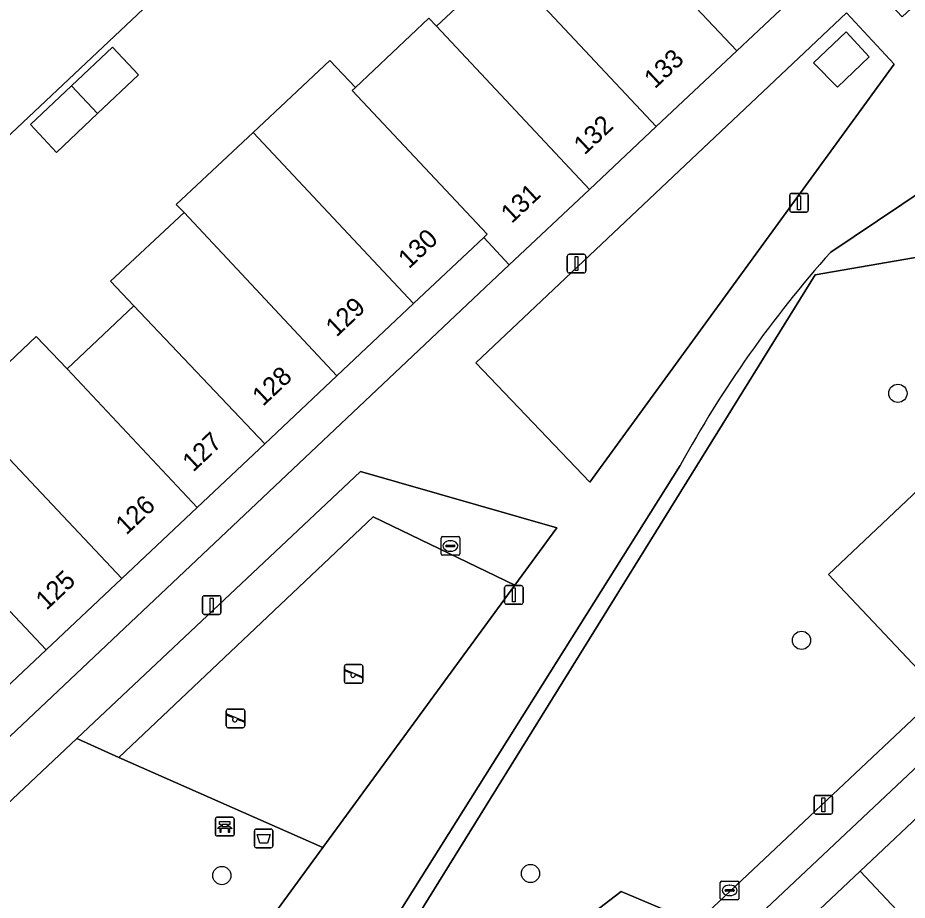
# Model space of a CAD drawing. Extents: x 162542 to 163147, y 380779 to 381521.
# Drawn here: x 162864.72 to 162912.36, y 381319.49 to 381366.74 of the extents above; entities that cross this region are included whole.
import ezdxf

# ---------------------------------------------------------------- set-up
doc = ezdxf.new("R2010")
doc.units = 0
for name, color, linetype in [('IMGEO_Afvalbak', 7, 'Continuous'), ('IMGEO_Bank', 7, 'Continuous'), ('IMGEO_Boom', 7, 'Continuous'), ('IMGEO_Erf', 7, 'Continuous'), ('IMGEO_Groenvoorziening', 7, 'Continuous'), ('IMGEO_Lage_trafo', 7, 'Continuous'), ('IMGEO_Lichtmast', 7, 'Continuous'), ('IMGEO_Muur', 7, 'Continuous'), ('IMGEO_Pand', 7, 'Continuous'), ('IMGEO_Pand_nummerreeks', 7, 'Continuous'), ('IMGEO_Rijbaan_lokaal_open', 7, 'Continuous'), ('IMGEO_Rioolput', 7, 'Continuous'), ('IMGEO_Speelvoorziening', 7, 'Continuous'), ('IMGEO_Terreindeel_halfverhard', 7, 'Continuous'), ('IMGEO_Terreindeel_zand', 7, 'Continuous'), ('IMGEO_Voetpad_open', 7, 'Continuous')]:
    doc.layers.add(name, color=color, linetype=linetype)

msp = doc.modelspace()

# ---------------------------------------------------------------- linework, layer by layer
at = {"layer": 'IMGEO_Afvalbak'}
for p, q in [((162877.394, 381322.396), (162877.394, 381323.196)), ((162877.394, 381323.196), (162877.394, 381322.396)), ((162877.494, 381323.296), (162878.284, 381323.296)), ((162878.284, 381323.296), (162877.494, 381323.296)), ((162878.384, 381323.196), (162878.384, 381322.396)), ((162878.384, 381322.396), (162878.384, 381323.196)), ((162878.284, 381322.296), (162877.494, 381322.296)), ((162877.494, 381322.296), (162878.284, 381322.296))]:
    msp.add_line(p, q, dxfattribs=at)
msp.add_lwpolyline([(162877.537, 381323.01), (162878.241, 381323.01), (162878.092, 381322.54), (162877.686, 381322.54), (162877.537, 381323.01)], dxfattribs=at)
for centre, start, end in [((162877.494, 381323.196), 90, 180), ((162877.494, 381323.196), 90, 180), ((162878.284, 381323.196), 0, 90), ((162878.284, 381323.196), 360, 90), ((162877.494, 381322.396), 180, 270), ((162877.494, 381322.396), 180, 270), ((162878.284, 381322.396), 270, 0), ((162878.284, 381322.396), 270, 0)]:
    msp.add_arc(centre, 0.1, start, end, dxfattribs=at)
at = {"layer": 'IMGEO_Bank'}
for p, q in [((162875.383, 381323.929), (162876.224, 381323.929)), ((162876.224, 381323.929), (162875.383, 381323.929)), ((162875.308, 381323.004), (162875.308, 381323.845)), ((162875.308, 381323.845), (162875.308, 381323.004)), ((162875.617, 381323.435), (162875.617, 381323.541)), ((162875.661, 381323.541), (162875.661, 381323.435)), ((162875.949, 381323.547), (162875.667, 381323.547)), ((162875.667, 381323.429), (162875.949, 381323.429)), ((162875.955, 381323.435), (162875.955, 381323.541)), ((162875.999, 381323.541), (162875.999, 381323.435)), ((162876.308, 381323.854), (162876.308, 381323.013)), ((162876.308, 381323.013), (162876.308, 381323.854)), ((162876.233, 381322.929), (162875.392, 381322.929)), ((162875.392, 381322.929), (162876.233, 381322.929)), ((162876.005, 381323.327), (162875.612, 381323.327))]:
    msp.add_line(p, q, dxfattribs=at)
for points in [[(162875.555, 381323.327), (162875.413, 381323.327), (162875.525, 381323.429), (162875.611, 381323.429)], [(162875.611, 381323.547), (162875.525, 381323.547), (162875.525, 381323.708), (162876.088, 381323.708), (162876.088, 381323.547), (162876.005, 381323.547)], [(162876.005, 381323.429), (162876.088, 381323.429), (162876.2, 381323.327), (162876.061, 381323.327)], [(162875.605, 381323.32), (162875.605, 381323.113), (162875.562, 381323.113), (162875.562, 381323.32)], [(162876.055, 381323.32), (162876.055, 381323.113), (162876.011, 381323.113), (162876.011, 381323.32)]]:
    msp.add_lwpolyline(points, dxfattribs=at)
for centre, radius, start, end in [((162875.386, 381323.851), 0.0779, 92.4484, 184.2845), ((162875.386, 381323.851), 0.0779, 92.4484, 184.2845), ((162876.23, 381323.851), 0.0779, 2.4484, 94.2845), ((162876.23, 381323.851), 0.0779, 2.4484, 94.2845), ((162875.61, 381323.54), 0.00671, 2.8957, 87.1043), ((162875.61, 381323.436), 0.00671, 272.8957, 357.1043), ((162875.667, 381323.54), 0.00671, 92.8957, 177.1043), ((162875.667, 381323.436), 0.00671, 182.8957, 267.1043), ((162875.949, 381323.54), 0.00671, 2.8957, 87.1043), ((162875.949, 381323.436), 0.00671, 272.8957, 357.1043), ((162876.006, 381323.54), 0.00671, 92.8957, 177.1043), ((162876.006, 381323.436), 0.00671, 182.8957, 267.1043), ((162875.386, 381323.007), 0.0779, 182.4484, 274.2845), ((162875.386, 381323.007), 0.0779, 182.4484, 274.2845), ((162875.555, 381323.32), 0.00671, 2.8957, 87.1043), ((162875.612, 381323.32), 0.00671, 92.8957, 177.1043), ((162876.004, 381323.32), 0.00671, 2.8957, 87.1043), ((162876.061, 381323.32), 0.00671, 92.8957, 177.1043), ((162876.23, 381323.007), 0.0779, 272.4484, 4.2845), ((162876.23, 381323.007), 0.0779, 272.4484, 4.2845)]:
    msp.add_arc(centre, radius, start, end, dxfattribs=at)
at = {"layer": 'IMGEO_Boom'}
for centre in [(162911.86, 381346.632), (162906.699, 381333.405), (162875.652, 381320.811), (162892.183, 381320.919)]:
    msp.add_circle(centre, 0.489, dxfattribs=at)
at = {"layer": 'IMGEO_Erf'}
for points in [[(162861.666, 381345.864), (162865.712, 381349.675), (162867.365, 381347.936), (162870.931, 381351.325), (162869.684, 381352.638), (162873.627, 381356.311), (162873.21, 381356.749), (162877.326, 381360.606), (162881.442, 381364.463), (162882.807, 381363.015), (162886.744, 381366.725), (162887.154, 381366.288), (162890.733, 381369.645), (162890.331, 381370.066), (162894.25, 381373.761), (162886.791, 381381.672), (162855.45, 381352.176)], [(162905.782, 381317.223), (162909.837, 381321.042), (162913.891, 381324.86), (162917.946, 381328.679), (162922.001, 381332.498), (162926.056, 381336.316), (162930.11, 381340.134), (162936.277, 381333.59), (162932.362, 381329.894), (162932.225, 381329.766), (162928.171, 381325.946), (162924.117, 381322.127), (162920.063, 381318.307)]]:
    msp.add_lwpolyline(points, dxfattribs=at)
for points in [[(162903.602, 381372.816), (162899.488, 381368.95), (162903.238, 381364.975), (162907.347, 381368.838)], [(162865.396, 381361.022), (162867.596, 381363.095), (162869.797, 381365.168), (162871.195, 381363.682), (162868.996, 381361.609), (162866.796, 381359.535)], [(162891.046, 381353.514), (162889.678, 381354.977), (162885.919, 381351.436), (162881.812, 381347.569), (162877.951, 381343.933), (162874.332, 381340.524), (162870.286, 381336.713), (162866.24, 381332.903), (162862.194, 381329.093), (162858.378, 381325.499), (162854.56, 381321.903), (162850.743, 381318.308), (162846.452, 381314.267), (162847.862, 381312.771)], [(162942.956, 381330.887), (162939.759, 381327.928), (162937.622, 381330.249), (162940.788, 381333.18), (162938.258, 381335.857), (162930.94, 381343.649), (162873.818, 381289.875), (162880.071, 381283.181), (162886.067, 381276.815), (162886.269, 381276.967), (162890.823, 381281.229), (162891.956, 381280.018), (162891.424, 381279.52), (162892.33, 381278.552), (162888.308, 381274.789), (162889.625, 381273.425), (162889.429, 381273.239), (162902.331, 381259.587), (162950.027, 381304.513), (162959.44, 381313.384), (162948.902, 381324.556), (162946.542, 381327.046), (162943.123, 381330.71)]]:
    msp.add_lwpolyline(points, close=True, dxfattribs=at)
at = {"layer": 'IMGEO_Groenvoorziening'}
for points in [[(162911.663, 381364.261), (162909.099, 381367.007), (162889.263, 381348.267), (162895.354, 381341.874)], [(162908.617, 381363.019), (162907.339, 381364.331), (162909.095, 381365.996), (162910.327, 381364.652)], [(162914.15, 381354.131), (162907.437, 381352.98), (162883.712, 381314.744), (162887.377, 381312.568), (162897.045, 381319.956), (162901.06, 381318.269), (162914.139, 381330.573), (162908.14, 381336.93), (162918.45, 381346.658), (162924.439, 381340.275), (162929.552, 381345.117), (162920.048, 381355.142)], [(162891.337, 381336.354), (162893.592, 381339.437), (162883.077, 381342.45), (162867.886, 381328.147), (162870.141, 381327.128), (162883.762, 381340.015)], [(162881.067, 381322.31), (162870.141, 381327.128), (162867.886, 381328.147), (162845.981, 381307.523), (162859.527, 381293.151), (162865.246, 381300.672)]]:
    msp.add_lwpolyline(points, close=True, dxfattribs=at)
msp.add_lwpolyline([(162900.206, 381342.771), (162872.763, 381299.129), (162870.795, 381295.515), (162871.434, 381295.246), (162882.08, 381312.238), (162883.712, 381314.744), (162907.437, 381352.98), (162914.15, 381354.131), (162913.608, 381357.077), (162915.016, 381357.986), (162914.563, 381358.416), (162908.261, 381354.192)], dxfattribs=at)
msp.add_arc((162953.374, 381313.824), 60.537, 138.17695, 151.43397, dxfattribs=at)
at = {"layer": 'IMGEO_Lage_trafo'}
msp.add_lwpolyline([(162910.327, 381364.652), (162909.095, 381365.996), (162907.339, 381364.331), (162908.617, 381363.019)], close=True, dxfattribs=at)
at = {"layer": 'IMGEO_Lichtmast'}
for p, q in [((162906.069, 381356.436), (162906.069, 381357.236)), ((162906.069, 381357.236), (162906.069, 381356.436)), ((162906.169, 381357.336), (162906.959, 381357.336)), ((162906.959, 381357.336), (162906.169, 381357.336)), ((162907.059, 381357.236), (162907.059, 381356.436)), ((162907.059, 381356.436), (162907.059, 381357.236)), ((162906.959, 381356.336), (162906.169, 381356.336)), ((162906.169, 381356.336), (162906.959, 381356.336)), ((162894.154, 381353.178), (162894.154, 381353.978)), ((162894.154, 381353.978), (162894.154, 381353.178)), ((162894.254, 381354.078), (162895.044, 381354.078)), ((162895.044, 381354.078), (162894.254, 381354.078)), ((162895.144, 381353.978), (162895.144, 381353.178)), ((162895.144, 381353.178), (162895.144, 381353.978)), ((162895.044, 381353.078), (162894.254, 381353.078)), ((162894.254, 381353.078), (162895.044, 381353.078)), ((162890.896, 381336.338), (162891.686, 381336.338)), ((162891.686, 381336.338), (162890.896, 381336.338)), ((162874.713, 381335.794), (162875.503, 381335.794)), ((162875.503, 381335.794), (162874.713, 381335.794)), ((162890.796, 381335.438), (162890.796, 381336.238)), ((162890.796, 381336.238), (162890.796, 381335.438)), ((162891.786, 381336.238), (162891.786, 381335.438)), ((162891.786, 381335.438), (162891.786, 381336.238)), ((162874.613, 381334.894), (162874.613, 381335.694)), ((162874.613, 381335.694), (162874.613, 381334.894)), ((162875.603, 381335.694), (162875.603, 381334.894)), ((162875.603, 381334.894), (162875.603, 381335.694)), ((162891.686, 381335.338), (162890.896, 381335.338)), ((162890.896, 381335.338), (162891.686, 381335.338)), ((162875.503, 381334.794), (162874.713, 381334.794)), ((162874.713, 381334.794), (162875.503, 381334.794)), ((162907.374, 381324.203), (162907.374, 381325.003)), ((162907.374, 381325.003), (162907.374, 381324.203)), ((162907.474, 381325.103), (162908.264, 381325.103)), ((162908.264, 381325.103), (162907.474, 381325.103)), ((162908.364, 381325.003), (162908.364, 381324.203)), ((162908.364, 381324.203), (162908.364, 381325.003)), ((162908.264, 381324.103), (162907.474, 381324.103)), ((162907.474, 381324.103), (162908.264, 381324.103))]:
    msp.add_line(p, q, dxfattribs=at)
for points in [[(162906.489, 381357.211), (162906.639, 381357.211), (162906.639, 381356.461), (162906.489, 381356.461), (162906.489, 381357.211)], [(162894.574, 381353.953), (162894.724, 381353.953), (162894.724, 381353.203), (162894.574, 381353.203), (162894.574, 381353.953)], [(162891.216, 381336.213), (162891.366, 381336.213), (162891.366, 381335.463), (162891.216, 381335.463), (162891.216, 381336.213)], [(162875.033, 381335.669), (162875.183, 381335.669), (162875.183, 381334.919), (162875.033, 381334.919), (162875.033, 381335.669)], [(162907.794, 381324.978), (162907.944, 381324.978), (162907.944, 381324.228), (162907.794, 381324.228), (162907.794, 381324.978)]]:
    msp.add_lwpolyline(points, dxfattribs=at)
for centre, start, end in [((162906.169, 381357.236), 90, 180), ((162906.169, 381357.236), 90, 180), ((162906.959, 381357.236), 0, 90), ((162906.959, 381357.236), 360, 90), ((162906.169, 381356.436), 180, 270), ((162906.169, 381356.436), 180, 270), ((162906.959, 381356.436), 270, 0), ((162906.959, 381356.436), 270, 0), ((162894.254, 381353.978), 90, 180), ((162894.254, 381353.978), 90, 180), ((162895.044, 381353.978), 0, 90), ((162895.044, 381353.978), 360, 90), ((162894.254, 381353.178), 180, 270), ((162894.254, 381353.178), 180, 270), ((162895.044, 381353.178), 270, 0), ((162895.044, 381353.178), 270, 0), ((162890.896, 381336.238), 90, 180), ((162890.896, 381336.238), 90, 180), ((162891.686, 381336.238), 0, 90), ((162891.686, 381336.238), 360, 90), ((162874.713, 381335.694), 90, 180), ((162874.713, 381335.694), 90, 180), ((162875.503, 381335.694), 0, 90), ((162875.503, 381335.694), 360, 90), ((162890.896, 381335.438), 180, 270), ((162890.896, 381335.438), 180, 270), ((162891.686, 381335.438), 270, 0), ((162891.686, 381335.438), 270, 0), ((162874.713, 381334.894), 180, 270), ((162874.713, 381334.894), 180, 270), ((162875.503, 381334.894), 270, 0), ((162875.503, 381334.894), 270, 0), ((162907.474, 381325.003), 90, 180), ((162907.474, 381325.003), 90, 180), ((162908.264, 381325.003), 0, 90), ((162908.264, 381325.003), 360, 90), ((162907.474, 381324.203), 180, 270), ((162907.474, 381324.203), 180, 270), ((162908.264, 381324.203), 270, 0), ((162908.264, 381324.203), 270, 0)]:
    msp.add_arc(centre, 0.1, start, end, dxfattribs=at)
at = {"layer": 'IMGEO_Muur'}
msp.add_lwpolyline([(162883.712, 381314.744), (162907.437, 381352.98), (162914.15, 381354.131)], dxfattribs=at)
at = {"layer": 'IMGEO_Pand'}
for points in [[(162899.488, 381368.95), (162899.302, 381368.775), (162894.444, 381373.944), (162894.25, 381373.761), (162890.331, 381370.066), (162890.733, 381369.645), (162898.92, 381360.916), (162903.238, 381364.975)], [(162890.733, 381369.645), (162887.154, 381366.288), (162895.345, 381357.555), (162898.92, 381360.916)], [(162887.154, 381366.288), (162886.744, 381366.725), (162882.807, 381363.015), (162882.624, 381362.842), (162889.865, 381355.153), (162889.678, 381354.977), (162891.046, 381353.514), (162895.345, 381357.555)], [(162871.195, 381363.682), (162869.797, 381365.168), (162867.596, 381363.095), (162868.996, 381361.609)], [(162882.624, 381362.842), (162882.807, 381363.015), (162881.442, 381364.463), (162877.326, 381360.606), (162885.919, 381351.436), (162889.678, 381354.977), (162889.865, 381355.153)], [(162867.596, 381363.095), (162865.396, 381361.022), (162866.796, 381359.535), (162868.996, 381361.609)], [(162877.326, 381360.606), (162873.21, 381356.749), (162873.627, 381356.311), (162881.812, 381347.569), (162885.919, 381351.436)], [(162873.627, 381356.311), (162869.684, 381352.638), (162870.931, 381351.325), (162877.951, 381343.933), (162881.812, 381347.569)], [(162870.931, 381351.325), (162867.365, 381347.936), (162874.332, 381340.524), (162877.951, 381343.933)], [(162867.365, 381347.936), (162865.712, 381349.675), (162861.666, 381345.864), (162870.286, 381336.713), (162874.332, 381340.524)], [(162861.666, 381345.864), (162857.621, 381342.054), (162866.24, 381332.903), (162870.286, 381336.713)], [(162857.621, 381342.054), (162853.575, 381338.243), (162855.218, 381336.499), (162862.194, 381329.093), (162866.24, 381332.903)], [(162909.837, 381321.042), (162916.008, 381314.488), (162920.063, 381318.307), (162913.891, 381324.86)], [(162911.954, 381310.668), (162916.008, 381314.488), (162909.837, 381321.042), (162905.782, 381317.223)]]:
    msp.add_lwpolyline(points, close=True, dxfattribs=at)
at = {"layer": 'IMGEO_Rijbaan_lokaal_open'}
msp.add_lwpolyline([(162886.791, 381381.672), (162891.278, 381385.908), (162887.127, 381390.321), (162882.996, 381386.44), (162882.238, 381385.728), (162865.763, 381370.246), (162864.683, 381369.231), (162864.202, 381368.779), (162863.244, 381367.866), (162846.747, 381352.149), (162845.83, 381351.275), (162844.405, 381349.917), (162827.898, 381334.19), (162831.86, 381329.93), (162855.45, 381352.176)], close=True, dxfattribs=at)
at = {"layer": 'IMGEO_Rioolput'}
for p, q in [((162887.393, 381338.032), (162887.393, 381338.884)), ((162887.468, 381338.958), (162888.32, 381338.958)), ((162887.881, 381338.738), (162887.906, 381338.738)), ((162888.394, 381338.884), (162888.394, 381338.032)), ((162887.652, 381338.452), (162887.652, 381338.464)), ((162888.09, 381338.415), (162887.692, 381338.415)), ((162887.695, 381338.501), (162888.093, 381338.501)), ((162887.904, 381338.178), (162887.879, 381338.178)), ((162888.136, 381338.464), (162888.136, 381338.452)), ((162888.32, 381337.958), (162887.468, 381337.958)), ((162902.349, 381319.589), (162902.349, 381320.441)), ((162902.424, 381320.515), (162903.276, 381320.515)), ((162902.651, 381320.058), (162903.049, 381320.058)), ((162902.837, 381320.295), (162902.862, 381320.295)), ((162903.35, 381320.441), (162903.35, 381319.589)), ((162902.608, 381320.009), (162902.608, 381320.021)), ((162903.046, 381319.972), (162902.648, 381319.972)), ((162902.86, 381319.735), (162902.835, 381319.735)), ((162903.092, 381320.021), (162903.092, 381320.009)), ((162903.276, 381319.515), (162902.424, 381319.515))]:
    msp.add_line(p, q, dxfattribs=at)
for points in [[(162887.393, 381338.032), (162887.393, 381338.884)], [(162887.468, 381338.958), (162888.32, 381338.958)], [(162888.394, 381338.884), (162888.394, 381338.032)], [(162888.32, 381337.958), (162887.468, 381337.958)], [(162902.349, 381319.589), (162902.349, 381320.441)], [(162902.424, 381320.515), (162903.276, 381320.515)], [(162903.35, 381320.441), (162903.35, 381319.589)], [(162903.276, 381319.515), (162902.424, 381319.515)]]:
    msp.add_lwpolyline(points, dxfattribs=at)
for centre, radius, start, end in [((162887.47, 381338.882), 0.0765, 91.552, 178.448), ((162887.47, 381338.882), 0.0765, 91.552, 178.448), ((162888.318, 381338.882), 0.0765, 1.552, 88.448), ((162888.318, 381338.882), 0.0765, 1.552, 88.448), ((162887.692, 381338.461), 0.0403, 85.8775, 175.7526), ((162887.689, 381338.451), 0.0366, 178.938, 274.7102), ((162888.093, 381338.458), 0.043, 264.8664, 352.4533), ((162888.097, 381338.463), 0.0386, 1.7309, 96.639), ((162887.47, 381338.034), 0.0765, 181.552, 268.448), ((162887.47, 381338.034), 0.0765, 181.552, 268.448), ((162888.318, 381338.034), 0.0765, 271.552, 358.448), ((162888.318, 381338.034), 0.0765, 271.552, 358.448), ((162902.426, 381320.439), 0.0765, 91.552, 178.448), ((162902.426, 381320.439), 0.0765, 91.552, 178.448), ((162902.648, 381320.018), 0.0403, 85.8775, 175.7526), ((162903.053, 381320.02), 0.0386, 1.7309, 96.639), ((162903.274, 381320.439), 0.0765, 1.552, 88.448), ((162903.274, 381320.439), 0.0765, 1.552, 88.448), ((162902.426, 381319.591), 0.0765, 181.552, 268.448), ((162902.426, 381319.591), 0.0765, 181.552, 268.448), ((162902.645, 381320.008), 0.0366, 178.938, 274.7102), ((162903.049, 381320.015), 0.043, 264.8664, 352.4533), ((162903.274, 381319.591), 0.0765, 271.552, 358.448), ((162903.274, 381319.591), 0.0765, 271.552, 358.448)]:
    msp.add_arc(centre, radius, start, end, dxfattribs=at)
for centre, major_axis, ratio, start_param, end_param in [((162887.88, 381338.458), (-0.387, 0.002), 0.722429, 4.712389, 7.853982), ((162887.905, 381338.458), (-0.39, 0.002), 0.717154, 1.570796, 4.712389), ((162902.836, 381320.015), (-0.387, 0.002), 0.722429, 4.712389, 7.853982), ((162902.861, 381320.015), (-0.39, 0.002), 0.717154, 1.570796, 4.712389)]:
    msp.add_ellipse(centre, major_axis=major_axis, ratio=ratio, start_param=start_param, end_param=end_param, dxfattribs=at)
at = {"layer": 'IMGEO_Speelvoorziening'}
for p, q in [((162882.212, 381331.204), (162882.212, 381332.004)), ((162882.212, 381332.004), (162882.212, 381331.204)), ((162882.312, 381332.104), (162883.102, 381332.104)), ((162883.102, 381332.104), (162882.312, 381332.104)), ((162883.202, 381332.004), (162883.202, 381331.204)), ((162883.202, 381331.204), (162883.202, 381332.004)), ((162882.595, 381331.632), (162882.256, 381331.769)), ((162882.281, 381331.829), (162883.157, 381331.476)), ((162883.133, 381331.416), (162882.793, 381331.553)), ((162883.102, 381331.104), (162882.312, 381331.104)), ((162882.312, 381331.104), (162883.102, 381331.104)), ((162875.884, 381328.823), (162875.884, 381329.623)), ((162875.884, 381329.623), (162875.884, 381328.823)), ((162875.984, 381329.723), (162876.774, 381329.723)), ((162876.774, 381329.723), (162875.984, 381329.723)), ((162876.874, 381329.623), (162876.874, 381328.823)), ((162876.874, 381328.823), (162876.874, 381329.623)), ((162876.267, 381329.251), (162875.928, 381329.388)), ((162875.953, 381329.448), (162876.829, 381329.095)), ((162876.805, 381329.035), (162876.465, 381329.172)), ((162876.774, 381328.723), (162875.984, 381328.723)), ((162875.984, 381328.723), (162876.774, 381328.723))]:
    msp.add_line(p, q, dxfattribs=at)
for centre, radius, start, end in [((162882.312, 381332.004), 0.1, 90, 180), ((162882.312, 381332.004), 0.1, 90, 180), ((162883.102, 381332.004), 0.1, 0, 90), ((162883.102, 381332.004), 0.1, 360, 90), ((162882.269, 381331.799), 0.0327, 68.078, 248.078), ((162882.674, 381331.542), 0.12, 130.9928, 5.1632), ((162882.312, 381331.204), 0.1, 180, 270), ((162882.312, 381331.204), 0.1, 180, 270), ((162883.102, 381331.204), 0.1, 270, 0), ((162883.102, 381331.204), 0.1, 270, 0), ((162883.145, 381331.446), 0.0327, 248.078, 68.078), ((162875.984, 381329.623), 0.1, 90, 180), ((162875.984, 381329.623), 0.1, 90, 180), ((162876.774, 381329.623), 0.1, 0, 90), ((162876.774, 381329.623), 0.1, 360, 90), ((162875.941, 381329.418), 0.0327, 68.078, 248.078), ((162876.346, 381329.161), 0.12, 130.9928, 5.1632), ((162875.984, 381328.823), 0.1, 180, 270), ((162875.984, 381328.823), 0.1, 180, 270), ((162876.774, 381328.823), 0.1, 270, 0), ((162876.774, 381328.823), 0.1, 270, 0), ((162876.817, 381329.065), 0.0327, 248.078, 68.078)]:
    msp.add_arc(centre, radius, start, end, dxfattribs=at)
at = {"layer": 'IMGEO_Terreindeel_halfverhard'}
msp.add_lwpolyline([(162914.139, 381330.573), (162924.439, 381340.275), (162918.45, 381346.658), (162908.14, 381336.93)], close=True, dxfattribs=at)
at = {"layer": 'IMGEO_Terreindeel_zand'}
msp.add_lwpolyline([(162891.337, 381336.354), (162883.762, 381340.015), (162870.141, 381327.128), (162881.067, 381322.31)], close=True, dxfattribs=at)
at = {"layer": 'IMGEO_Voetpad_open'}
for points in [[(162908.261, 381354.192), (162914.563, 381358.416), (162915.016, 381357.986), (162918.286, 381360.097), (162917.198, 381361.262), (162921.606, 381365.289), (162916.402, 381370.801), (162912.094, 381366.787), (162908.744, 381370.37), (162896.201, 381383.789), (162893.039, 381387.172), (162891.278, 381385.908), (162903.602, 381372.816), (162907.347, 381368.838), (162903.238, 381364.975), (162898.92, 381360.916), (162895.345, 381357.555), (162891.046, 381353.514), (162847.862, 381312.771)], [(162872.763, 381299.129), (162900.206, 381342.771)]]:
    msp.add_lwpolyline(points, dxfattribs=at)
for points in [[(162889.263, 381348.267), (162909.099, 381367.007), (162911.663, 381364.261), (162895.354, 381341.874)], [(162930.94, 381343.649), (162929.552, 381345.117), (162924.439, 381340.275), (162914.139, 381330.573), (162901.06, 381318.269), (162897.045, 381319.956), (162887.377, 381312.568), (162883.712, 381314.744), (162882.08, 381312.238), (162887.971, 381305.961), (162872.439, 381291.347), (162873.818, 381289.875)], [(162845.981, 381307.523), (162867.886, 381328.147), (162883.077, 381342.45), (162893.592, 381339.437), (162891.337, 381336.354), (162881.067, 381322.31), (162865.246, 381300.672), (162866.239, 381294.068), (162862.21, 381290.304), (162859.527, 381293.151)]]:
    msp.add_lwpolyline(points, close=True, dxfattribs=at)
msp.add_arc((162953.374, 381313.824), 60.537, 138.17695, 151.43397, dxfattribs=at)

# ---------------------------------------------------------------- texts
at = {"layer": 'IMGEO_Pand_nummerreeks'}
for s, rotation, p in [('133', 43.2297, (162898.846, 381362.904)), ('132', 43.2354, (162895.073, 381359.358)), ('131', 43.2297, (162891.173, 381355.691)), ('130', 43.287, (162885.674, 381353.267)), ('129', 43.2755, (162881.788, 381349.607)), ('128', 43.2812, (162877.858, 381345.906)), ('127', 43.287, (162874.116, 381342.382)), ('126', 43.287, (162870.535, 381339.009)), ('125', 43.2812, (162866.259, 381334.982))]:
    msp.add_text(s, height=1, rotation=rotation, dxfattribs=at).set_placement(p)

doc.saveas('drawing.dxf')
